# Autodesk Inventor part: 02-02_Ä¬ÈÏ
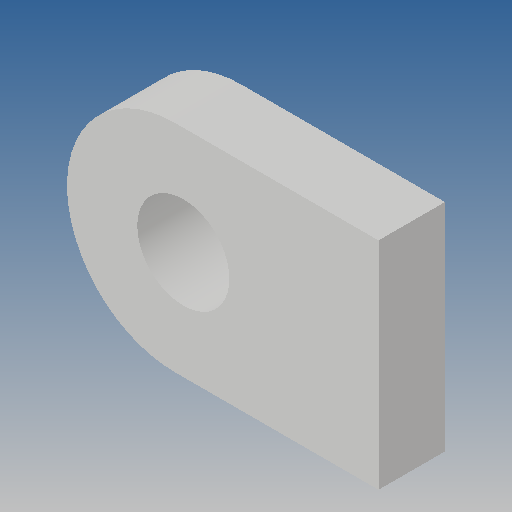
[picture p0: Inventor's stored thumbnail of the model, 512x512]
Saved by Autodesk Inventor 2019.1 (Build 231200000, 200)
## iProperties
Created: 2010-06
Part Number: 02-02_Ä¬ÈÏ
Material: Ogólny
Document SubType Name: Modeling
Designer: CADENGINEERING4
Density: 1 g/cm^3
Appearance: Domyślna
Author: CADENGINEERING4
Revision Number: ÈÎºÎ
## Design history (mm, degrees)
feature "NONE"
node "Bryła1"
